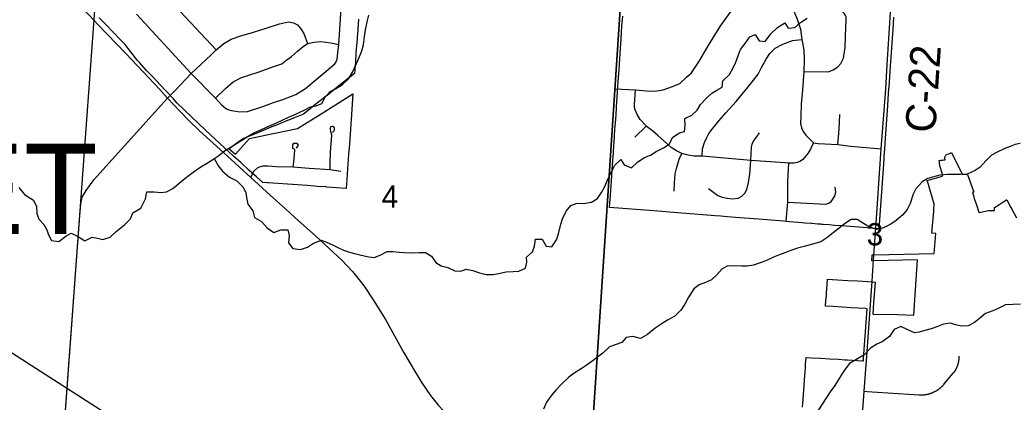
# Model space of a CAD drawing. Extents: x 0 to 34, y 0 to 26.1.
# Drawn here: x 25.464 to 27.339, y 15.199 to 15.919 of the extents above; entities that cross this region are included whole.
import ezdxf

# ---------------------------------------------------------------- set-up
doc = ezdxf.new("R2010")
doc.units = 0
for name, color, linetype in [('GM_X_County_Road', 7, 'Continuous'), ('GM_X_County_Road_Text', 7, 'Continuous'), ('GM_X_Minor_River', 7, 'Continuous'), ('GM_X_Rail_Line', 7, 'Continuous'), ('GM_X_Section', 7, 'Continuous'), ('GM_X_Section_Text', 7, 'Continuous'), ('GM_X_State_Route', 7, 'Continuous'), ('GM_X_Township_Road', 7, 'Continuous'), ('GM_X_Township_Text', 7, 'Continuous'), ('SC_Scratch1', 7, 'Continuous')]:
    doc.layers.add(name, color=color, linetype=linetype)

msp = doc.modelspace()

# ---------------------------------------------------------------- linework, layer by layer
at = {"layer": 'GM_X_County_Road'}
for p, q in [((27.0723, 15.4671), (27.0765, 15.527)), ((27.0696, 15.4272), (27.0716, 15.4572)), ((27.0716, 15.4572), (27.0723, 15.4671))]:
    msp.add_line(p, q, dxfattribs=at)
for points in [[(27.0981, 15.8354), (27.1037, 15.9232), (27.1095, 16.024), (27.1253, 16.2152), (27.136, 16.402), (27.1519, 16.5743), (27.1604, 16.6746), (27.1631, 16.7041), (27.1645, 16.7321), (27.1669, 16.7607), (27.1823, 16.9679), (27.1942, 17.1333), (27.1967, 17.1739), (27.2024, 17.2543), (27.2067, 17.3105), (27.2105, 17.3599), (27.2149, 17.4267), (27.2235, 17.5489)], [(27.0765, 15.527), (27.0868, 15.6765), (27.0952, 15.789), (27.0981, 15.8354)], [(27.0409, 15.0278), (27.0437, 15.0687), (27.0546, 15.2196), (27.0598, 15.2857), (27.0696, 15.4272)]]:
    msp.add_lwpolyline(points, dxfattribs=at)
at = {"layer": 'GM_X_Minor_River'}
for points in [[(26.1021, 15.8475), (26.1079, 15.8611), (26.1111, 15.8724), (26.1132, 15.8872), (26.1149, 15.9005), (26.1178, 15.916), (26.121, 15.9281)], [(26.7883, 15.8046), (26.801, 15.8166), (26.8076, 15.8287), (26.813, 15.8396), (26.8178, 15.8536), (26.8217, 15.8638), (26.8302, 15.8747), (26.8394, 15.8874), (26.8493, 15.8915), (26.8564, 15.8796), (26.8677, 15.8787), (26.8789, 15.893), (26.8915, 15.9053), (26.9049, 15.9139), (26.9112, 15.9035), (26.9237, 15.9049), (26.9344, 15.9142), (26.947, 15.9224)], [(25.4617, 15.6032), (25.4725, 15.5901), (25.4893, 15.5797), (25.4952, 15.5674), (25.4954, 15.5545), (25.499, 15.5439), (25.5087, 15.5335), (25.5143, 15.5239), (25.5172, 15.5144), (25.5231, 15.5037), (25.5367, 15.5016), (25.5504, 15.5116), (25.56, 15.5176), (25.5724, 15.5117), (25.5859, 15.5032), (25.5996, 15.5098), (25.6098, 15.5078), (25.62, 15.5054), (25.634, 15.5101), (25.6448, 15.5206), (25.6609, 15.5329), (25.672, 15.5441), (25.6763, 15.5555), (25.6916, 15.5647), (25.7005, 15.5821), (25.703, 15.5953), (25.7166, 15.5951), (25.7291, 15.5938), (25.7401, 15.5952), (25.7519, 15.6015), (25.7672, 15.6145), (25.7776, 15.6227), (25.7902, 15.6321), (25.8043, 15.6421), (25.815, 15.6484), (25.8288, 15.6573), (25.8383, 15.6637), (25.849, 15.6726), (25.8651, 15.6819), (25.8765, 15.6893), (25.8937, 15.7001), (25.9055, 15.7068), (25.9177, 15.7123), (25.928, 15.7171), (25.9413, 15.7226), (25.9566, 15.73), (25.9695, 15.7359), (25.979, 15.7395), (25.9886, 15.7439), (26.0008, 15.7498), (26.0114, 15.7554), (26.0217, 15.7575), (26.0323, 15.7616), (26.0389, 15.774), (26.0482, 15.7845), (26.0581, 15.7897), (26.0715, 15.7978), (26.0833, 15.8087), (26.0903, 15.8211), (26.0978, 15.8373), (26.1021, 15.8475)], [(25.8294, 15.6578), (25.8377, 15.6436), (25.8455, 15.634), (25.8586, 15.6231), (25.8721, 15.6158), (25.884, 15.605), (25.8892, 15.5939), (25.8905, 15.5844), (25.8934, 15.5718), (25.9027, 15.5592), (25.9059, 15.5466), (25.9187, 15.5396), (25.9295, 15.5273), (25.9422, 15.5184), (25.9552, 15.5235), (25.9688, 15.5237), (25.9713, 15.513), (25.9699, 15.499), (25.9781, 15.4883), (25.9925, 15.4866), (26.0058, 15.4909), (26.0169, 15.4984), (26.0317, 15.5039), (26.0426, 15.4999), (26.0524, 15.4952), (26.0629, 15.4902), (26.0734, 15.4855), (26.0847, 15.4815), (26.0968, 15.4787), (26.107, 15.4759), (26.1209, 15.4727), (26.1311, 15.4718), (26.1426, 15.4762), (26.1555, 15.4828), (26.1665, 15.4827), (26.1782, 15.4817), (26.188, 15.4812), (26.2028, 15.4803), (26.216, 15.4808), (26.2278, 15.481), (26.239, 15.4737), (26.2476, 15.4622), (26.2573, 15.4556), (26.2701, 15.4524), (26.2829, 15.4465), (26.2943, 15.4456), (26.3045, 15.4496), (26.3174, 15.4468), (26.3294, 15.4425), (26.3422, 15.4396), (26.3555, 15.4394), (26.3653, 15.4416), (26.3801, 15.4444), (26.3934, 15.445), (26.404, 15.446), (26.4162, 15.4515), (26.419, 15.4629), (26.4184, 15.4723), (26.4295, 15.4824), (26.4331, 15.493), (26.4355, 15.5059), (26.4476, 15.5061), (26.4554, 15.4927), (26.466, 15.4918), (26.4745, 15.505), (26.4784, 15.5163), (26.4832, 15.5345), (26.4864, 15.5443), (26.493, 15.5586), (26.5019, 15.5695), (26.5137, 15.5739), (26.5254, 15.5733), (26.5406, 15.5758), (26.552, 15.5825), (26.5598, 15.5941), (26.5652, 15.6039), (26.573, 15.6216), (26.5777, 15.6318), (26.5847, 15.6458), (26.5962, 15.6559), (26.6025, 15.6459), (26.6161, 15.6408), (26.628, 15.652), (26.6406, 15.6602), (26.652, 15.6646), (26.6627, 15.6713), (26.6764, 15.6783), (26.6871, 15.6854), (26.6941, 15.6985), (26.7067, 15.7063), (26.7162, 15.7089), (26.7175, 15.7202), (26.7169, 15.7335), (26.7299, 15.7398), (26.7398, 15.7491), (26.7464, 15.7597), (26.7576, 15.7721), (26.7672, 15.781), (26.7767, 15.7866), (26.787, 15.7925), (26.7883, 15.8046)], [(27.3487, 15.6865), (27.3389, 15.6843), (27.3294, 15.6806), (27.3195, 15.6769), (27.305, 15.6702), (27.2947, 15.6643), (27.284, 15.6537), (27.2733, 15.6417), (27.2637, 15.6357), (27.2489, 15.6287), (27.236, 15.6277), (27.2114, 15.6279), (27.1973, 15.6266), (27.1875, 15.6244), (27.1745, 15.6203), (27.1639, 15.6144), (27.152, 15.6008), (27.1469, 15.591), (27.1411, 15.5733), (27.1353, 15.5619), (27.1272, 15.5518), (27.1146, 15.5413), (27.105, 15.5342), (27.091, 15.5275), (27.0792, 15.5242), (27.0645, 15.5285), (27.0535, 15.5358), (27.0411, 15.5432), (27.0301, 15.5433), (27.0176, 15.5351), (27.0072, 15.5268), (26.9962, 15.5178), (26.9843, 15.5088), (26.9729, 15.501)], [(26.9729, 15.501), (26.9413, 15.4921), (26.9288, 15.4892), (26.9147, 15.4841), (26.9052, 15.4801), (26.893, 15.4757), (26.8835, 15.472), (26.869, 15.465), (26.8584, 15.4613), (26.8458, 15.4573), (26.834, 15.4549), (26.8231, 15.455), (26.8098, 15.4559), (26.7966, 15.4554), (26.7867, 15.4502), (26.7767, 15.4386), (26.7667, 15.4296), (26.7557, 15.4244), (26.7439, 15.4197), (26.7335, 15.4122), (26.7227, 15.3957), (26.7165, 15.3836), (26.7091, 15.3723), (26.6976, 15.3607), (26.6842, 15.3533), (26.6739, 15.347), (26.6609, 15.3381), (26.646, 15.3265), (26.633, 15.3187), (26.6187, 15.3223), (26.6062, 15.321), (26.5981, 15.3112), (26.5875, 15.3076), (26.5745, 15.3032), (26.5623, 15.2912), (26.5523, 15.2834), (26.5412, 15.2752), (26.5305, 15.2678), (26.521, 15.2618), (26.508, 15.2533), (26.498, 15.2462), (26.4838, 15.2323), (26.4742, 15.2222), (26.4658, 15.2125), (26.4557, 15.199), (26.4503, 15.1857)], [(27.3489, 15.3836), (27.3345, 15.383), (27.3209, 15.3824), (27.3083, 15.3761), (27.2972, 15.3709), (27.2835, 15.3657), (27.2721, 15.3563), (27.2625, 15.3492), (27.2503, 15.3429), (27.2386, 15.3419), (27.2269, 15.3446), (27.2171, 15.3478), (27.2042, 15.346), (27.1912, 15.3408), (27.181, 15.3372), (27.1692, 15.3342), (27.1585, 15.3309), (27.1491, 15.3295), (27.1355, 15.3361), (27.1234, 15.3412), (27.1109, 15.3356), (27.102, 15.3228), (27.0886, 15.3127), (27.0784, 15.3079), (27.0665, 15.3004), (27.0543, 15.288), (27.0417, 15.2805), (27.0272, 15.2716), (27.0168, 15.2584), (27.0076, 15.2437), (26.9991, 15.2305), (26.9903, 15.2185), (26.9606, 15.1719)]]:
    msp.add_lwpolyline(points, dxfattribs=at)
at = {"layer": 'GM_X_Rail_Line'}
msp.add_lwpolyline([(27.301, 14.1), (27.0785, 14.2427), (26.9137, 14.3485), (26.2475, 14.7771), (25.9542, 14.966), (25.6567, 15.1572), (25.4759, 15.2734), (25.3538, 15.3521), (25.2892, 15.3938), (25.2593, 15.4116), (25.1825, 15.4531), (24.7379, 15.6913), (24.5774, 15.7768)], dxfattribs=at)
at = {"layer": 'GM_X_Section'}
for points in [[(25.6194, 16.135), (26.1174, 16.097), (26.603, 16.0634), (26.5367, 15.0651), (25.5463, 15.1393)], [(26.603, 16.0634), (26.6185, 16.0611), (27.1167, 16.0245), (27.6154, 15.9857), (27.5444, 14.9891), (26.5367, 15.0651)]]:
    msp.add_lwpolyline(points, close=True, dxfattribs=at)
at = {"layer": 'GM_X_State_Route'}
for points in [[(25.5408, 15.9845), (25.5464, 15.9789), (25.6041, 15.9174), (25.6097, 15.9115)], [(25.6097, 15.9115), (25.6636, 15.8554), (25.727, 15.7879), (25.7419, 15.7719)], [(25.7419, 15.7719), (25.7658, 15.7466), (25.7828, 15.7292), (25.8014, 15.7108), (25.8548, 15.6623)], [(25.8548, 15.6623), (25.8986, 15.6225), (25.9353, 15.5889), (25.9648, 15.5623)], [(25.9648, 15.5623), (25.981, 15.5477), (26.0211, 15.5118), (26.0465, 15.4884), (26.0704, 15.4662), (26.0902, 15.4448), (26.1031, 15.4296), (26.1124, 15.4174), (26.1293, 15.3918), (26.1523, 15.3544), (26.1867, 15.2931), (26.2066, 15.2594), (26.2208, 15.235), (26.2372, 15.2112), (26.2524, 15.1924), (26.2713, 15.1725), (26.2888, 15.1526), (26.3243, 15.1127), (26.3329, 15.1032), (26.3484, 15.0861), (26.3606, 15.0709), (26.3677, 15.0606)]]:
    msp.add_lwpolyline(points, dxfattribs=at)
at = {"layer": 'GM_X_Township_Road'}
for p, q in [((25.6085, 15.6239), (25.7419, 15.7719)), ((26.6223, 15.6983), (26.6439, 15.7193))]:
    msp.add_line(p, q, dxfattribs=at)
for points in [[(25.6738, 16.1311), (25.6679, 16.064), (25.6676, 16.0505), (25.6686, 16.0441), (25.6728, 16.0352), (25.6907, 16.015), (25.7171, 15.987), (25.8334, 15.8632)], [(26.9166, 16.0392), (26.9148, 16.0092), (26.9126, 15.9845), (26.913, 15.963), (26.9157, 15.9549), (26.9229, 15.9347), (26.9282, 15.9204), (26.9345, 15.902), (26.9373, 15.8827), (26.9408, 15.863), (26.9417, 15.845), (26.9407, 15.8223), (26.9385, 15.7878), (26.9359, 15.7603), (26.935, 15.7379), (26.9346, 15.7242), (26.9366, 15.7162), (26.9395, 15.709), (26.9446, 15.7023), (26.9592, 15.6879), (26.9677, 15.6866), (27.0047, 15.6842), (27.0293, 15.6814), (27.0868, 15.6765)], [(25.6835, 15.9301), (25.7861, 15.8182), (25.8319, 15.7716), (25.8441, 15.7584), (25.853, 15.7519), (25.8573, 15.7497), (25.8622, 15.7487), (25.8779, 15.7463), (25.8926, 15.7467), (25.9217, 15.7561), (25.9416, 15.7637), (25.9591, 15.7694), (25.9835, 15.7785), (26.0016, 15.7903), (26.018, 15.8041), (26.0409, 15.8225), (26.0569, 15.8367), (26.0595, 15.8402), (26.0612, 15.8455), (26.063, 15.8571), (26.0643, 15.8731), (26.0708, 15.97)], [(26.5845, 15.7895), (26.6236, 15.7878), (26.6445, 15.7859), (26.66, 15.7853), (26.6757, 15.7875), (26.6932, 15.7935), (26.7073, 15.7995), (26.7199, 15.8112), (26.7293, 15.8196), (26.7433, 15.8401), (26.7597, 15.8691), (26.7831, 15.9066), (26.805, 15.9374), (26.82, 15.9491), (26.8309, 15.9557), (26.8414, 15.9592), (26.8536, 15.9618), (26.8734, 15.9624), (26.8955, 15.963), (26.913, 15.963)], [(26.9407, 15.8223), (26.9871, 15.8217), (26.996, 15.8252), (27.0052, 15.8309), (27.0105, 15.8373), (27.0157, 15.8474), (27.019, 15.8672), (27.0199, 15.906), (27.0209, 15.9182), (27.0205, 15.925), (27.0197, 15.9276), (27.0172, 15.9307), (27.0138, 15.9347), (27.0071, 15.9394), (26.9958, 15.9438)], [(25.7419, 15.7719), (25.7555, 15.7856), (25.7861, 15.8182), (25.8236, 15.8531), (25.8334, 15.8632), (25.8476, 15.8751), (25.8615, 15.883), (25.88, 15.8893), (25.9037, 15.896), (25.9274, 15.9039), (25.953, 15.9118), (25.97, 15.9157), (25.9794, 15.9141), (25.9869, 15.9098), (25.9933, 15.9027), (25.9988, 15.894), (26.0055, 15.8747)], [(25.8319, 15.7716), (25.8508, 15.7902), (25.8658, 15.8024), (25.8812, 15.8107), (25.9128, 15.821), (25.942, 15.8312), (25.957, 15.8368), (25.9664, 15.8439), (25.9755, 15.8506), (25.9869, 15.8601), (25.9972, 15.8695), (26.0055, 15.8747), (26.0181, 15.8776), (26.031, 15.8784), (26.0497, 15.8759), (26.0643, 15.8731)], [(26.7491, 15.6623), (26.7498, 15.6762), (26.7538, 15.6881), (26.7581, 15.6977), (26.762, 15.7053), (26.768, 15.7136), (26.7816, 15.7298), (26.7941, 15.7444), (26.8134, 15.7653), (26.8415, 15.8002), (26.8547, 15.8171), (26.8608, 15.8293), (26.8699, 15.8455), (26.8767, 15.856), (26.8868, 15.8659), (26.9014, 15.8737), (26.9192, 15.8806), (26.9373, 15.8827)], [(26.9592, 15.6879), (26.9532, 15.6758), (26.9485, 15.6678), (26.9424, 15.6598), (26.9382, 15.6553), (26.9333, 15.6524), (26.9281, 15.6504), (26.9222, 15.6492), (26.9126, 15.649), (26.9055, 15.6499), (26.8411, 15.6542), (26.7491, 15.6623), (26.734, 15.6625), (26.723, 15.6644), (26.7108, 15.6676), (26.7011, 15.6728), (26.6907, 15.6786), (26.6775, 15.6909), (26.6659, 15.7016), (26.6559, 15.7103), (26.6439, 15.7193), (26.6445, 15.7193), (26.6326, 15.7319), (26.6268, 15.7413), (26.6229, 15.7497), (26.6216, 15.7542), (26.6216, 15.76), (26.6236, 15.7878)], [(27.0047, 15.6842), (27.0069, 15.7054), (27.008, 15.7258), (27.0085, 15.7408)], [(26.0481, 15.6371), (26.0485, 15.6493), (26.0491, 15.6702), (26.0515, 15.702), (26.0496, 15.7087), (26.0489, 15.7138), (26.0494, 15.7181), (26.0519, 15.719), (26.0539, 15.7183), (26.0557, 15.7158), (26.0557, 15.7129), (26.055, 15.7099), (26.0529, 15.7068)], [(26.8411, 15.6542), (26.8424, 15.6792), (26.8438, 15.6854), (26.8445, 15.6881), (26.848, 15.6934), (26.8531, 15.6999), (26.8575, 15.7065)], [(25.9787, 15.6421), (25.9803, 15.6569), (25.9811, 15.6664), (25.9819, 15.6729), (25.9816, 15.6748), (25.9778, 15.6771), (25.9778, 15.6839), (25.9801, 15.687), (25.9854, 15.687), (25.9877, 15.6831), (25.9843, 15.6774)], [(26.6965, 15.5965), (26.6969, 15.6117), (26.6985, 15.6289), (26.7011, 15.6395), (26.7062, 15.657), (26.7108, 15.6676)], [(25.8986, 15.6225), (25.9043, 15.6341), (25.9112, 15.6405), (25.9154, 15.6424), (25.9222, 15.6444), (25.9315, 15.6443), (25.9463, 15.6433), (25.9787, 15.6421), (26.0085, 15.6396), (26.0481, 15.6371), (26.0684, 15.6345)], [(26.7614, 15.6014), (26.7789, 15.5884), (26.7869, 15.5855), (26.7961, 15.5831), (26.8064, 15.5821), (26.8173, 15.5835), (26.8242, 15.5871), (26.8296, 15.5928), (26.8335, 15.5998), (26.8369, 15.6128), (26.8391, 15.6286), (26.8411, 15.6542)], [(26.9073, 15.5409), (26.9107, 15.5756), (26.9109, 15.6146), (26.9126, 15.649)], [(25.5761, 15.543), (25.5783, 15.5729), (25.5811, 15.5853), (25.5885, 15.5977), (25.6031, 15.618), (25.6085, 15.6239)], [(26.9107, 15.5756), (26.9822, 15.5722), (26.9877, 15.5737), (26.9925, 15.577), (26.9956, 15.5814), (26.999, 15.5879), (27.0009, 15.5946), (26.9999, 15.604)], [(25.4863, 14.3285), (25.5202, 14.7858), (25.5288, 14.9037), (25.5459, 15.1318), (25.5761, 15.543)], [(27.0546, 15.2196), (27.0602, 15.2192), (27.1573, 15.2126), (27.158, 15.2125), (27.1588, 15.2125), (27.1595, 15.2125), (27.1603, 15.2124), (27.161, 15.2124), (27.1618, 15.2124), (27.1626, 15.2124), (27.1633, 15.2125), (27.1641, 15.2125), (27.1648, 15.2125), (27.1656, 15.2126), (27.1663, 15.2127), (27.1671, 15.2127), (27.1678, 15.2128), (27.1686, 15.2129), (27.1693, 15.213), (27.1701, 15.2131), (27.1708, 15.2132), (27.1716, 15.2134), (27.1723, 15.2135), (27.1731, 15.2137), (27.1738, 15.2138), (27.1746, 15.214), (27.1753, 15.2142), (27.176, 15.2144), (27.1768, 15.2146), (27.1775, 15.2148), (27.1782, 15.215), (27.1789, 15.2152), (27.1796, 15.2155), (27.1804, 15.2157), (27.1811, 15.216), (27.1818, 15.2162), (27.1825, 15.2165), (27.1832, 15.2168), (27.1839, 15.2171), (27.1846, 15.2174), (27.1853, 15.2177), (27.186, 15.218), (27.1866, 15.2183), (27.1873, 15.2187), (27.188, 15.219), (27.1887, 15.2194), (27.1893, 15.2197), (27.19, 15.2201), (27.1906, 15.2205), (27.1913, 15.2209), (27.1919, 15.2213), (27.1926, 15.2217), (27.1932, 15.2221), (27.1938, 15.2225), (27.1945, 15.223), (27.1951, 15.2234), (27.1957, 15.2238), (27.1963, 15.2243), (27.1969, 15.2248), (27.1975, 15.2252), (27.1981, 15.2257), (27.1987, 15.2262), (27.1992, 15.2267), (27.1998, 15.2272), (27.2004, 15.2277), (27.2009, 15.2282), (27.2015, 15.2288), (27.202, 15.2293), (27.2025, 15.2298), (27.2031, 15.2304), (27.2036, 15.2309), (27.2041, 15.2315), (27.2046, 15.232), (27.2051, 15.2326), (27.2055, 15.2331), (27.2224, 15.2533), (27.2229, 15.2539), (27.2234, 15.2545), (27.2238, 15.2551), (27.2243, 15.2557), (27.2247, 15.2563), (27.2252, 15.2569), (27.2256, 15.2576), (27.226, 15.2582), (27.2264, 15.2588), (27.2268, 15.2595), (27.2272, 15.2601), (27.2276, 15.2608), (27.2279, 15.2615), (27.2283, 15.2621), (27.2286, 15.2628), (27.2289, 15.2635), (27.2292, 15.2642), (27.2296, 15.2649), (27.2299, 15.2656), (27.2301, 15.2663), (27.2304, 15.267), (27.2307, 15.2677), (27.2309, 15.2684), (27.2312, 15.2691), (27.2314, 15.2699), (27.2316, 15.2706), (27.2318, 15.2713), (27.232, 15.272), (27.2322, 15.2728), (27.2323, 15.2735), (27.2325, 15.2743), (27.2327, 15.275), (27.2328, 15.2758), (27.2329, 15.2765), (27.233, 15.2773), (27.2331, 15.278), (27.2332, 15.2788), (27.2333, 15.2795), (27.2333, 15.2803), (27.2334, 15.281), (27.2334, 15.2818), (27.2334, 15.2825), (27.2335, 15.2833), (27.2335, 15.284), (27.2334, 15.2853)]]:
    msp.add_lwpolyline(points, dxfattribs=at)
at = {"layer": 'SC_Scratch1'}
for points in [[(26.1017, 15.9206), (26.1003, 15.9018), (26.1002, 15.9), (26.0992, 15.8866), (26.0989, 15.8829), (26.098, 15.8709), (26.0975, 15.864), (26.0969, 15.8558), (26.0958, 15.8407), (26.0942, 15.8181), (26.0846, 15.8105), (26.0649, 15.7949), (26.0501, 15.7831), (26.0487, 15.7821), (26.0352, 15.7714), (26.0189, 15.7584), (26.01, 15.7513), (25.9982, 15.7419), (25.9791, 15.7342), (25.9779, 15.7337), (25.9615, 15.727), (25.944, 15.7198), (25.9432, 15.7195), (25.9323, 15.7151), (25.9264, 15.7127), (25.9089, 15.7055), (25.8942, 15.6995), (25.885, 15.6957), (25.8796, 15.6919), (25.8581, 15.6764), (25.8696, 15.6661), (25.896, 15.6955), (25.9376, 15.7043), (25.9469, 15.7062), (25.9865, 15.7146), (26.005, 15.7261), (26.021, 15.7361), (26.0581, 15.7591), (26.0913, 15.7799), (26.0878, 15.7317), (26.0872, 15.7232), (26.0858, 15.7037), (26.0844, 15.6848), (26.083, 15.6659), (26.0811, 15.6394), (26.0803, 15.6281), (26.0783, 15.6016), (26.0605, 15.6029), (26.042, 15.6043), (26.0403, 15.6044), (26.0235, 15.6056), (26.0189, 15.6059), (26.005, 15.6069), (25.9865, 15.6082), (25.968, 15.6096), (25.9494, 15.6109), (25.9309, 15.6122), (25.9294, 15.6123), (25.9214, 15.6128), (25.9094, 15.6237), (25.8953, 15.6364), (25.8803, 15.6498), (25.8663, 15.6624), (25.8131, 15.7112), (25.7601, 15.7625), (25.7522, 15.7709), (25.7393, 15.7848), (25.7277, 15.7972), (25.7147, 15.8111), (25.7018, 15.8249), (25.6889, 15.8388), (25.6843, 15.8436), (25.6769, 15.8535), (25.6653, 15.8686), (25.6613, 15.8739), (25.6527, 15.8827), (25.6395, 15.8963), (25.6262, 15.9098), (25.613, 15.9234)], [(27.1101, 15.9245), (27.1084, 15.9015), (27.1067, 15.876), (27.1047, 15.8483), (27.1037, 15.8327), (27.1029, 15.8212), (27.1015, 15.8024), (27.1014, 15.8007), (27.1, 15.781), (27.0984, 15.7579), (27.0935, 15.6867), (27.0927, 15.6765), (27.0917, 15.6617), (27.0915, 15.6587), (27.0915, 15.6583), (27.0907, 15.6472), (27.0822, 15.5254), (27.0765, 15.5259), (27.0709, 15.5263), (27.0685, 15.5265), (27.0522, 15.5278), (27.0131, 15.5309), (26.9991, 15.532), (26.9886, 15.5329), (26.9776, 15.5338), (26.9746, 15.534), (26.9731, 15.5341), (26.9673, 15.5346), (26.9557, 15.5355), (26.9544, 15.5356), (26.9428, 15.5365), (26.9368, 15.537), (26.9142, 15.5388), (26.9142, 15.5388), (26.9075, 15.5394), (26.9028, 15.5397), (26.8717, 15.5422), (26.8633, 15.5429), (26.8554, 15.5435), (26.8205, 15.5463), (26.7967, 15.5482), (26.7843, 15.5492), (26.7737, 15.55), (26.7348, 15.5531), (26.703, 15.5557), (26.6583, 15.5593), (26.5749, 15.5659), (26.5765, 15.5889), (26.5783, 15.6152), (26.5798, 15.6369), (26.581, 15.6539), (26.5811, 15.6554), (26.582, 15.669), (26.583, 15.6837), (26.5833, 15.6883), (26.5849, 15.7125), (26.5859, 15.7262), (26.5863, 15.7318), (26.5876, 15.7514), (26.5879, 15.7557), (26.5898, 15.7835), (26.5905, 15.7949), (26.5927, 15.826), (26.5947, 15.8559), (26.5966, 15.8838), (26.5982, 15.9076), (26.5995, 15.9265)], [(26.9385, 15.1895), (26.9395, 15.2036), (26.9421, 15.2399), (26.9422, 15.2416), (26.9432, 15.2558), (26.9438, 15.2635), (26.9442, 15.27), (26.9451, 15.2832), (26.955, 15.2826), (26.972, 15.2816), (26.9891, 15.2806), (27.0061, 15.2796), (27.0179, 15.2789), (27.0231, 15.2786), (27.0509, 15.277), (27.0532, 15.2768), (27.0535, 15.2803), (27.0602, 15.375), (27.0578, 15.3751), (27.0302, 15.3768), (27.0132, 15.3778), (26.9962, 15.3789), (26.9819, 15.3797), (26.9826, 15.3906), (26.9833, 15.3999), (26.9836, 15.4051), (26.9841, 15.4118), (26.9854, 15.4307), (27.0043, 15.4295), (27.0045, 15.4295), (27.0235, 15.4284), (27.0425, 15.4273), (27.0614, 15.4261), (27.0695, 15.4256), (27.0751, 15.4253), (27.074, 15.4095), (27.0723, 15.3858), (27.0708, 15.3648), (27.1176, 15.3638), (27.1479, 15.3631), (27.1512, 15.4104), (27.1532, 15.4389), (27.1552, 15.4673), (27.0723, 15.4651), (27.0689, 15.465), (27.0697, 15.4764), (27.0731, 15.4765), (27.1865, 15.479), (27.1897, 15.5168), (27.1823, 15.5175), (27.1857, 15.5588), (27.1861, 15.5634), (27.1867, 15.5718), (27.1757, 15.6089), (27.1734, 15.6166), (27.1996, 15.6244), (27.2023, 15.6252), (27.203, 15.6254), (27.2009, 15.6321), (27.1978, 15.6425), (27.197, 15.6457), (27.1965, 15.6489), (27.1963, 15.651), (27.1958, 15.6544), (27.1984, 15.6547), (27.2015, 15.6551), (27.2046, 15.6555), (27.2071, 15.6558), (27.2067, 15.6589), (27.2067, 15.66), (27.2068, 15.6611), (27.2072, 15.6622), (27.2077, 15.6632), (27.2084, 15.6641), (27.2092, 15.6649), (27.2101, 15.6655), (27.2112, 15.666), (27.2144, 15.6672), (27.2176, 15.6686), (27.2192, 15.6694), (27.23, 15.6476), (27.2397, 15.6282), (27.2489, 15.6284), (27.249, 15.6281), (27.2611, 15.5946), (27.2585, 15.5937), (27.2603, 15.5883), (27.2621, 15.583), (27.264, 15.5774), (27.2663, 15.5708), (27.2709, 15.5572), (27.2712, 15.5563), (27.289, 15.5603), (27.3004, 15.5603), (27.3003, 15.563), (27.3, 15.5656), (27.3015, 15.5665), (27.3036, 15.5679), (27.3105, 15.5723), (27.3199, 15.5783), (27.3229, 15.5802), (27.3234, 15.5805), (27.3311, 15.5658), (27.3326, 15.5628), (27.3414, 15.546)]]:
    msp.add_lwpolyline(points, dxfattribs=at)

# ---------------------------------------------------------------- texts
at = {"layer": 'GM_X_County_Road_Text'}
msp.add_text('C-22', height=0.05682, rotation=86.2318, dxfattribs=at).set_placement((27.1885, 15.7055))
at = {"layer": 'GM_X_Section_Text'}
for s, p in [('4', (26.1454, 15.5656)), ('3', (27.0592, 15.4944))]:
    msp.add_text(s, height=0.0419, rotation=0, dxfattribs=at).set_placement(p)
at = {"layer": 'GM_X_Township_Text'}
msp.add_text('VIOLET', height=0.17045, rotation=0, dxfattribs=at).set_placement((24.7995, 15.5156))

doc.saveas('drawing.dxf')
